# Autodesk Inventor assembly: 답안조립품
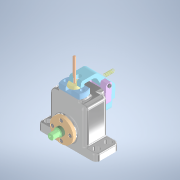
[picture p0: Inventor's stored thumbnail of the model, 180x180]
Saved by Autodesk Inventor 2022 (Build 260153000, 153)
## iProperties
Created: 2023-12
Part Number: 답안조립품
Document SubType Name: Assembly
Designer: PC-01
Author: PC-01
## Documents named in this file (14)
- C:\Users\PC-01\Desktop\731208V1019\답안조립품.iam
- C:\Users\PC-01\Desktop\731208V1019\본체.ipt
- C:\Users\PC-01\Desktop\731208V1019\가이드 부시.ipt
- C:\Users\PC-01\Desktop\731208V1019\조절 부시.ipt
- C:\Users\PC-01\Desktop\731208V1019\클램프 샤프트.ipt
- C:\Users\PC-01\Desktop\731208V1019\고정대.ipt
- C:\Users\PC-01\Desktop\731208V1019\육각 소켓 머리 볼트 M3 x 8.ipt
- C:\Users\PC-01\Desktop\731208V1019\가공품.ipt
- C:\Users\PC-01\Desktop\731208V1019\브라켓.ipt
- C:\Users\PC-01\Desktop\731208V1019\클램프.ipt
- C:\Users\PC-01\Desktop\731208V1019\육각 머리 볼트 M6 x 12.ipt
- C:\Users\PC-01\Desktop\731208V1019\육각 소켓 머리 볼트 M3 x 30.ipt
- C:\Users\PC-01\Desktop\731208V1019\핀.ipt
- C:\Users\PC-01\Desktop\731208V1019\스프링.ipt
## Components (4 placed, 4 different names)
1. 가이드 부시:1
2. 고정대:1
3. 가공품:1
4. 핀:1
